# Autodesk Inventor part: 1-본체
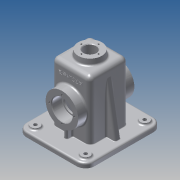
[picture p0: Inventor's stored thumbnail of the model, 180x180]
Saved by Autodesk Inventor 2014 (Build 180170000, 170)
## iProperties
Created: 2015-12
Part Number: 1-본체
Material: 알루미늄 6061
Document SubType Name: Modeling
Designer: Administrator
Density: 2.71 g/cm^3
Appearance: 알루미늄 - 평지
Mass: 806.269 g
Surface Area: 909.625 cm^2
Volume: 297.516 cm^3
Author: Administrator
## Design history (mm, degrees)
sketch "스케치1"
  geometry: L1 (-50, -57.5)-(50, -57.5); L2 (65, -42.5)-(65, 42.5); L3 (50, 57.5)-(-50, 57.5); L4 (-65, 42.5)-(-65, -42.5); A1 r 15 centre (-50, 42.5) between (-50, 57.5) and (-65, 42.5); A2 r 15 centre (-50, -42.5) between (-65, -42.5) and (-50, -57.5); A3 r 15 centre (50, -42.5) between (50, -57.5) and (65, -42.5); A4 r 15 centre (50, 42.5) between (65, 42.5) and (50, 57.5); 7 further points
  constraints: 8 end point, 8 point on circle, 8 point on line, 8 tangent, 4 centre point, 3 equal radius, 2 midpoint, 2 parallel, 1 horizontal, 1 horizontal alignment, 1 perpendicular, 1 vertical alignment
  dimensions: "d0" = 130 distance of point (-65, 57.5) point (65, 57.5); "d1" = 115 distance of point (65, 57.5) point (65, -57.5); "d4" = 15 radius of A1
extrude "돌출1" new body sketch "스케치1" distance "d2" = 8; taper "d3" = 0 deg
sketch "스케치2"
  geometry: L1 (50, 57.5)-(-50, 57.5) reference; L2 (-65, 42.5)-(-65, -42.5) reference; L3 (-50, -57.5)-(50, -57.5) reference; L4 (65, -42.5)-(65, 42.5) reference; L5 (-50, 52.5)-(50, 52.5); L6 (60, 42.5)-(60, -42.5); L7 (50, -52.5)-(-50, -52.5); L8 (-60, -42.5)-(-60, 42.5); A1 r 15 centre (-50, 42.5) between (-50, 57.5) and (-65, 42.5) reference; A2 r 15 centre (-50, -42.5) between (-65, -42.5) and (-50, -57.5) reference; A3 r 15 centre (50, -42.5) between (50, -57.5) and (65, -42.5) reference; A4 r 15 centre (50, 42.5) between (65, 42.5) and (50, 57.5) reference; A5 r 10 centre (50, 42.5) between (60, 42.5) and (50, 52.5); A6 r 10 centre (50, -42.5) between (50, -52.5) and (60, -42.5); A7 r 10 centre (-50, -42.5) between (-60, -42.5) and (-50, -52.5); A8 r 10 centre (-50, 42.5) between (-50, 52.5) and (-60, 42.5); 1 further point
  constraints: 8 end point, 8 point on circle, 4 centre point, 7 other
  dimensions: "d5" = 5 distance between parallel lines of L2 L8
extrude "돌출2" join sketch "스케치2" distance "d6" = 2; taper "d7" = 0 deg
sketch "스케치3"
  geometry: L1 (50, 57.5)-(-50, 57.5) reference; L2 (65, -42.5)-(65, 42.5) reference; C1 r 7.5 at (-50, 42.5); C2 r 7.5 at (50, 42.5); C3 r 7.5 at (-50, -42.5); C4 r 7.5 at (50, -42.5); A1 r 15 centre (-50, 42.5) between (-50, 57.5) and (-65, 42.5) reference; 1 further point
  constraints: 4 centre point, 1 coincident, 1 horizontal, 1 vertical, 6 other
  dimensions: "d8" = 15 diameter of C1; "d11" = 100 distance of C1.centre C2.centre; "d14" = 85 distance of C1.centre C3.centre
extrude "돌출3" join sketch "스케치3" distance "d17" = 3; taper "d18" = 0 deg
hole "구멍1" diameter "d21" = 6; stored, may be unused: countersink angle "d25" = 90 deg, drill point angle "d27" = 118 deg; dims "d19" = 10, "d20" = 10, "d22" = 6, "d23" = 4, "d24" = 2, "d26" = 8
hole "구멍2" diameter "d30" = 6; stored, may be unused: countersink angle "d34" = 90 deg, drill point angle "d36" = 118 deg; dims "d28" = 10, "d29" = 10, "d31" = 6, "d32" = 4, "d33" = 2, "d35" = 8
hole "구멍3" diameter "d39" = 6; stored, may be unused: countersink angle "d43" = 90 deg, drill point angle "d45" = 118 deg; dims "d37" = 10, "d38" = 10, "d40" = 6, "d41" = 4, "d42" = 2, "d44" = 8
hole "구멍4" diameter "d48" = 6; stored, may be unused: countersink angle "d52" = 90 deg, drill point angle "d54" = 118 deg; dims "d46" = 10, "d47" = 10, "d49" = 6, "d50" = 4, "d51" = 2, "d53" = 8
sketch "스케치4"
  geometry: L1 (-32.5, -32.5)-(32.5, -32.5); L2 (32.5, -32.5)-(32.5, 32.5); L3 (32.5, 32.5)-(-32.5, 32.5); L4 (-32.5, 32.5)-(-32.5, -32.5); L5 (-32.5, -32.5)-(32.5, 32.5); L6 (32.5, -32.5)-(-32.5, 32.5); 1 further point
  constraints: 12 end point, 2 midpoint, 2 parallel, 1 horizontal, 1 perpendicular
  dimensions: "d55" = 65 distance of L3.end L2.end; "d56" = 65 distance of L2.end L1.end
extrude "돌출4" join sketch "스케치4" distance "d57" = 100; taper "d58" = 0 deg
node "작업 평면1"
sketch "스케치5"
  geometry: C1 r 20 at (0, 0); 1 further point
  constraints: 1 centre point, 1 coincident
  dimensions: "d59" = 40 diameter of C1
extrude "돌출5" join sketch "스케치5" distance "d60" = 10; taper "d61" = 5 deg
sketch "스케치6"
  geometry: L1 (-100, 0)-(-100, 65) reference; L2 (10, 75)-(10, -10) reference; C1 r 27.5 at (-45, 32.5); 2 further points
  constraints: 1 centre point, 1 horizontal alignment, 1 midpoint
  dimensions: "d62" = 55 diameter of C1; "d63" = 55 distance from line of L2 C1.centre
extrude "돌출6" join sketch "스케치6" distance "d64" = 15; taper "d65" = 0 deg
hole "구멍5" diameter "d68" = 30; stored, may be unused: countersink angle "d72" = 90 deg, drill point angle "d74" = 118 deg; dims "d66" = 10, "d67" = 10, "d69" = 6, "d70" = 35, "d71" = 17, "d73" = 8
sketch "스케치7"
  geometry: C1 r 17.5 at (0, 0) reference; 2 further points
  constraints: 1 horizontal alignment
  dimensions: "d75" = 21 distance of C1.centre point (-21, 0)
hole "구멍6" sketch "스케치7" at (-21, 0) diameter "d76" = 3.242; stored, may be unused: countersink angle "d80" = 90 deg, drill point angle "d82" = 118 deg; dims "d77" = 8, "d78" = 35, "d79" = 17, "d81" = 10
hole "구멍7" diameter "d88" = 21; stored, may be unused: countersink angle "d92" = 90 deg, drill point angle "d94" = 118 deg; dims "d89" = 8, "d90" = 35, "d91" = 17, "d93" = 10, "d142" = 10, "d143" = 10
sketch "스케치9"
  geometry: L1 (-57.5, 0)-(-57.5, 8) reference; L2 (-57.5, 8)-(-32.5, 8) reference; L3 (-32.5, 8)-(-32.5, 108) reference; L4 (-32.5, 108)-(-20.875, 108) reference; L5 (-10.5, -2)-(-52.5, -2) reference; L6 (-52.5, -2)-(-52.5, 0) reference; L7 (-52.5, 0)-(-57.5, 0) reference; L8 (57.5, 8)-(57.5, 0) reference; L9 (57.5, 0)-(52.5, 0) reference; L10 (52.5, 0)-(52.5, -2) reference; L11 (20.875, 108)-(32.5, 108) reference; L12 (32.5, 108)-(32.5, 8) reference; L13 (32.5, 8)-(57.5, 8) reference; L14 (-32.5, 93.069)-(-47.5, 8); L15 (-20.875, 108)-(-20, 118) reference; L16 (-20, 118)-(-10.5, 118) reference; L17 (20, 118)-(20.875, 108) reference; L18 (-10.5, 118)-(-10.5, 63.712) reference; L19 (-10.5, 42.288)-(-10.5, -2) reference; L20 (52.5, -2)-(10.5, -2) reference; L21 (10.5, -2)-(10.5, 42.288) reference; L22 (10.5, 63.712)-(10.5, 118) reference; L23 (10.5, 118)-(20, 118) reference; A1 r 15 centre (0, 53) between (-10.5, 63.712) and (-10.5, 42.288) reference; A2 r 15 centre (0, 53) between (10.5, 42.288) and (10.5, 63.712) reference; 1 further point
  constraints: 2 end point, 2 point on line
  dimensions: "d107" = 10 distance from line of L14.end L1; "d109" = 10 deg angle of L14 L1
feature "리브1" sketch "스케치9" dims "d110" = 1, "d111" = 10, "d112" = 0, "d113" = 0, "d114" = 1, "d115" = 1
sketch "스케치10"
  geometry: L1 (-27.5, -27.5)-(27.5, -27.5); L2 (27.5, -27.5)-(27.5, 27.5); L3 (27.5, 27.5)-(-27.5, 27.5); L4 (-27.5, 27.5)-(-27.5, -27.5); L5 (-27.5, -27.5)-(27.5, 27.5); L6 (27.5, -27.5)-(-27.5, 27.5); C1 r 10.5 at (0, 0) reference
  constraints: 12 end point, 2 midpoint, 2 parallel, 1 horizontal, 1 perpendicular
  dimensions: "d116" = 55 distance of L3.end L2.end; "d117" = 55 distance of L2.end L1.end
extrude "돌출7" cut sketch "스케치10" distance "d118" = 105; taper "d119" = 0 deg
sketch "스케치11"
  geometry: L1 (32.5, 80.5)-(47.5, 80.5) reference; L2 (47.5, 80.5)-(47.5, 75.621) reference; L3 (47.5, 75.621)-(37.5, 75.621) reference; L4 (37.5, 75.621)-(36.526, 74) reference; L5 (36.526, 74)-(37.5, 72.379) reference; L6 (37.5, 72.379)-(47.5, 72.379) reference; L7 (47.5, 72.379)-(47.5, 70.5) reference; L8 (47.5, 70.5)-(30.5, 70.5) reference; L9 (30.5, 70.5)-(30.5, 68) reference; L10 (30.5, 68)-(27.5, 68) reference; L11 (27.5, 68)-(27.5, 103) reference; L12 (27.5, 103)-(10.5, 103) reference; L13 (20.875, 108)-(32.5, 108) reference; L14 (32.5, 108)-(32.5, 80.5) reference; L15 (47.5, 25.5)-(32.5, 25.5) reference; L16 (32.5, 25.5)-(32.5, 8) reference; L17 (32.5, 8)-(65, 8) reference; L18 (65, 8)-(65, 0) reference; L19 (65, 0)-(60, 0) reference; L20 (60, 0)-(60, -2) reference; L21 (60, -2)-(27.5, -2) reference; L22 (27.5, -2)-(27.5, 38) reference; L23 (27.5, 38)-(30.5, 38) reference; L24 (30.5, 38)-(30.5, 35.5) reference; L25 (30.5, 35.5)-(47.5, 35.5) reference; L26 (47.5, 35.5)-(47.5, 33.621) reference; L27 (47.5, 33.621)-(37.5, 33.621) reference; L28 (37.5, 33.621)-(36.526, 32) reference; L29 (36.526, 32)-(37.5, 30.379) reference; L30 (37.5, 30.379)-(47.5, 30.379) reference; L31 (47.5, 30.379)-(47.5, 25.5) reference; L32 (-47.5, 80.5)-(-32.5, 80.5) reference; L33 (-32.5, 80.5)-(-32.5, 108) reference; L34 (-32.5, 108)-(-20.875, 108) reference; L35 (-10.5, 103)-(-27.5, 103) reference; L36 (-27.5, 103)-(-27.5, 68) reference; L37 (-27.5, 68)-(-30.5, 68) reference; L38 (-30.5, 68)-(-30.5, 70.5) reference; L39 (-30.5, 70.5)-(-47.5, 70.5) reference; L40 (-47.5, 70.5)-(-47.5, 72.379) reference; L41 (-47.5, 72.379)-(-37.5, 72.379) reference; L42 (-37.5, 72.379)-(-36.526, 74) reference; L43 (-36.526, 74)-(-37.5, 75.621) reference; L44 (-37.5, 75.621)-(-47.5, 75.621) reference; L45 (-47.5, 75.621)-(-47.5, 80.5) reference; L46 (-32.5, 25.5)-(-47.5, 25.5) reference; L47 (-47.5, 25.5)-(-47.5, 30.379) reference; L48 (-47.5, 30.379)-(-37.5, 30.379) reference; L49 (-37.5, 30.379)-(-36.526, 32) reference; L50 (-36.526, 32)-(-37.5, 33.621) reference; L51 (-37.5, 33.621)-(-47.5, 33.621) reference; L52 (-47.5, 33.621)-(-47.5, 35.5) reference; L53 (-47.5, 35.5)-(-30.5, 35.5) reference; L54 (-30.5, 35.5)-(-30.5, 38) reference; L55 (-30.5, 38)-(-27.5, 38) reference; L56 (-27.5, 38)-(-27.5, -2) reference; L57 (-27.5, -2)-(-60, -2) reference; L58 (-60, -2)-(-60, 0) reference; L59 (-60, 0)-(-65, 0) reference; L60 (-65, 0)-(-65, 8) reference; L61 (-65, 8)-(-32.5, 8) reference; L62 (-32.5, 8)-(-32.5, 25.5) reference; L63 (-42.5, 25.5)-(-42.5, 8); L64 (-20.875, 108)-(-20, 118) reference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; 1 further point
  constraints: 2 end point, 2 point on line, 1 perpendicular
  dimensions: "d120" = 15 distance between parallel lines of L56 L63
feature "리브2" sketch "스케치11" dims "d122" = 1, "d123" = 6, "d124" = 0, "d125" = 0, "d126" = 1, "d127" = 1
fillet "모깎기1" dims "d128" = 8
fillet "모깎기2" dims "d129" = 0.3
chamfer "모따기1" distance "d130" = 1; stored, may be unused: second distance "d131" = 2, angle "d132" = 45 deg
fillet "모깎기3" dims "d133" = 3
fillet "모깎기4" dims "d134" = 3
fillet "모깎기5" dims "d135" = 1
fillet "모깎기6" dims "d136" = 3
sketch "스케치12"
  geometry: L1 (0, -8)-(91, -8) reference; L2 (-18, 4.5)-(-18, 44.5) reference; 2 further points
  constraints: 1 other
  dimensions: "d138" = 32.5 distance from line of point (8, 24.5) L1; "d155" = 26 distance from line of point (8, 24.5) L2
feature "엠보싱1" sketch "스케치12" dims "d139" = 0.5, "d140" = 0
sketch "스케치13"
  geometry: C1 r 10.5 at (0, 0) reference; 1 further point
  constraints: 1 vertical alignment
  dimensions: "d144" = 14.5 distance of C1.centre point (0, 14.5)
hole "구멍9" sketch "스케치13" at (0, 14.5) diameter "d145" = 2.459; stored, may be unused: countersink angle "d149" = 90 deg, drill point angle "d151" = 118 deg; dims "d146" = 7, "d147" = 4, "d148" = 2, "d150" = 9
node "솔리드1"
pattern_circular "원형 패턴1" dims angle "d84" = 360 deg
mirror "대칭1"
mirror "대칭2"
mirror "대칭3"
pattern_circular "원형 패턴3" dims angle "d153" = 360 deg
node "절단 모서리 투영1"
node "절단 모서리 투영2"
